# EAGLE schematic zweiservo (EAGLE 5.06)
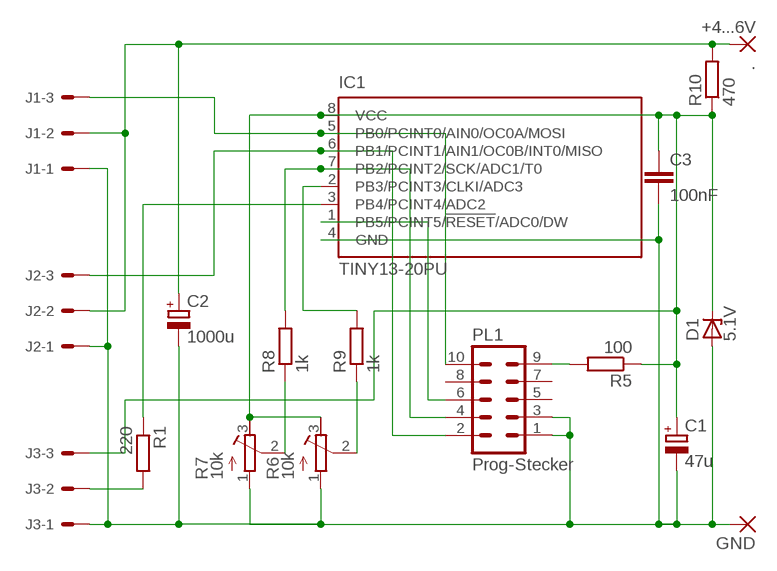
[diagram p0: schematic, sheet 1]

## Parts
.  +4...6V  WIREPAD3,81/1,1  [3,81/1,1]
C1  47u  CPOL-EUE3.5-8  [E3,5-8]
C2  1000u  CPOL-EUE3.5-8  [E3,5-8]
C3  100nF  C-EU050-024X044  [C050-024X044]
D1  5.1V  ZENER-DIODEC1702-15  [C1702-15]
GND  WIREPAD3,81/1,1  [3,81/1,1]
IC1  TINY13-20PU  [DIL08]
J1  22-27-2031-03  [6410-03]
J2  22-27-2031-03  [6410-03]
J3  22-27-2031-03  [6410-03]
PL1  Prog-Stecker  10V  [10V]
R1  220  R-EU_0204/7  [0204/7]
R5  100  R-EU_0204/7  [0204/7]
R6  10k  R-TRIMM3339P  [RTRIM3339P]
R7  10k  R-TRIMM3339P  [RTRIM3339P]
R8  1k  R-EU_0204/7  [0204/7]
R9  1k  R-EU_0204/7  [0204/7]
R10  470  R-EU_0204/7  [0204/7]

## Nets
GND: C1.- C2.- C3.2 D1.A GND.1(P) IC1.4(GND) J1.1 J2.1 J3.1 PL1.1 PL1.3 R6.1(E) R7.1(E)
N$1: J3.2 R1.2
N$2: ..1(P) C2.+ J1.2 J2.2 R10.2
N$3: IC1.3(PB4/PCINT4/ADC2) R1.1
N$5: IC1.6(PB1/PCINT1/AIN1/OC0B/INT0/MISO) J2.3 PL1.2
N$6: IC1.5(PB0/PCINT0/AIN0/OC0A/MOSI) J1.3 PL1.10
N$10: PL1.9 R5.2
N$11: IC1.7(PB2/PCINT2/SCK/ADC1/T0) PL1.4 R8.2
N$12: IC1.2(PB3/PCINT3/CLKI/ADC3) R9.2
N$13: R7.2(S) R8.1
N$14: R6.2(S) R9.1
N$15: IC1.1(PB5/PCINT5/!RESET!/ADC0/DW) PL1.6
VCC: C1.+ C3.1 D1.C IC1.8(VCC) J3.3 R5.1 R6.3(A) R7.3(A) R10.1
Unconnected: PL1.5 PL1.7 PL1.8

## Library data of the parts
. GND = wirepad:WIREPAD: Wire PAD connect wire on PCB
C1 C2 = rcl:CPOL-EU: POLARIZED CAPACITOR, European symbol
C3 = rcl:C-EU: CAPACITOR, European symbol
D1 = diode:ZENER-DIODE: Z-Diode
IC1 = atmel:TINY13: 8-bit AVR Microcontroller with 1K Bytes In-System Programmable Flash Source: http://www.atmel.com/dyn/resources/prod_documents/2535S.pdf
J1-J3 = con-molex:22-?-03: CONNECTOR wire to board 2.54 mm (.1 inch) pitch header
PL1 = con-harting-v:10V: CONNECTOR
R1 R5 R8-R10 = rcl:R-EU_: RESISTOR, European symbol
R6 R7 = rcl:R-TRIMM: Trimm resistor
